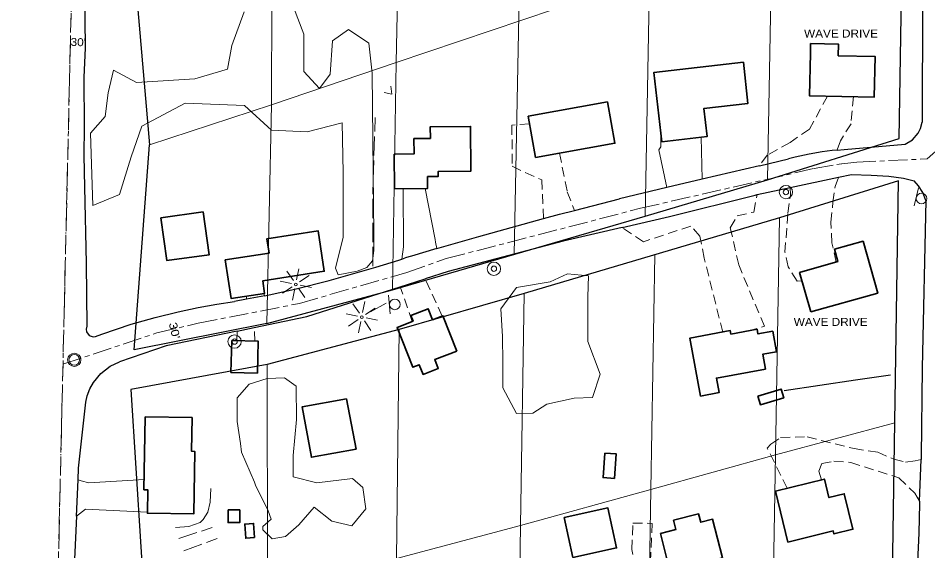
# Model space of a CAD drawing. Extents: x -861682 to -858969, y -1797841 to -1795153.
# Drawn here: x -861677 to -860995, y -1796483 to -1796083 of the extents above; entities that cross this region are included whole.
import ezdxf

# ---------------------------------------------------------------- set-up
doc = ezdxf.new("R2010")
doc.units = 0
doc.header["$LTSCALE"] = 2.4
for name, pattern in [('DOT_DASHED', [7.7, 5, -1.2, 0.3, -1.2]), ('LONG_DASH_SHORT_DASH', [9.9, 6, -1.2, 1.5, -1.2]), ('LONG_DASHED', [7.5, 6, -1.5]), ('MEDIUM_DASHED', [4.5, 3, -1.5])]:
    doc.linetypes.add(name, pattern=pattern)
for name, color, linetype, lineweight in [('10', 7, 'Continuous', 25), ('11', 7, 'Continuous', 13), ('12', 7, 'Continuous', 35), ('14', 7, 'Continuous', 25), ('17', 7, 'Continuous', 13), ('18', 7, 'Continuous', 13), ('21', 7, 'Continuous', 13), ('30', 7, 'Continuous', 13), ('31', 7, 'Continuous', 13), ('32', 7, 'LONG_DASH_SHORT_DASH', 13), ('36', 7, 'Continuous', 13), ('37', 7, 'Continuous', 13), ('42', 7, 'Continuous', 25), ('46', 7, 'Continuous', 13), ('52', 7, 'LONG_DASHED', 13), ('61', 7, 'Continuous', 13)]:
    doc.layers.add(name, color=color, linetype=linetype, lineweight=lineweight)
doc.layers.add('43', color=7, linetype='Continuous')

msp = doc.modelspace()

# ---------------------------------------------------------------- linework, layer by layer
at = {"layer": '10'}
for p, q in [((-860998.917, -1796071.72), (-860998.986, -1796161.04)), ((-861057.643, -1796181.638), (-861011.836, -1796177.693)), ((-861062.884, -1796182.084), (-861057.643, -1796181.638)), ((-861121.116, -1796193.796), (-861099.17, -1796188.618)), ((-861121.116, -1796193.796), (-861164.05, -1796203.927)), ((-861164.05, -1796203.927), (-861190.523, -1796210.174)), ((-861190.523, -1796210.174), (-861226.034, -1796218.554)), ((-861389.178, -1796263.819), (-861386.564, -1796262.963)), ((-861491.879, -1796291.281), (-861505.478, -1796293.954)), ((-861505.478, -1796293.954), (-861514.586, -1796295.745)), ((-861512.641, -1796317.835), (-861499.825, -1796315.144)), ((-861000.983, -1796445.525), (-860999.845, -1796414.115)), ((-861632.978, -1796456.776), (-861631.833, -1796429.359))]:
    msp.add_line(p, q, dxfattribs=at)
for points in [[(-861626.717, -1796064.684), (-861626.785, -1796084.061), (-861626.599, -1796105.326), (-861627.586, -1796127.546), (-861627.262, -1796164.642), (-861627.547, -1796186.147), (-861627.104, -1796209.773), (-861625.659, -1796266.943), (-861625.247, -1796314.198)], [(-861011.836, -1796177.693), (-861006.222, -1796174.249), (-861001.937, -1796169.248), (-861000.248, -1796165.865), (-860998.986, -1796161.04)], [(-861062.884, -1796182.084), (-861066.426, -1796182.387), (-861074.079, -1796183.353), (-861083.855, -1796185.016), (-861094.334, -1796187.346), (-861099.17, -1796188.618)], [(-861122.807, -1796215.423), (-861097.992, -1796210.128), (-861061.784, -1796202.403)], [(-861061.784, -1796202.403), (-861052.101, -1796200.338), (-861037.221, -1796200.751), (-861023.992, -1796201.642), (-861013.123, -1796203.016), (-861005.085, -1796205.108)], [(-860996.34, -1796219.944), (-860998.578, -1796213.737), (-861001.692, -1796208.773), (-861005.085, -1796205.108)], [(-861282.823, -1796233.418), (-861270.848, -1796230.126), (-861259.703, -1796227.248), (-861226.034, -1796218.554)], [(-861223.961, -1796240.056), (-861188.477, -1796231.823), (-861124.305, -1796215.743), (-861122.807, -1796215.423)], [(-860996.34, -1796219.944), (-860999.09, -1796345.364), (-860999.768, -1796411.964), (-860999.845, -1796414.115)], [(-861362.844, -1796255.976), (-861331.414, -1796246.777), (-861282.823, -1796233.418)], [(-861223.961, -1796240.056), (-861268.227, -1796250.327), (-861354.335, -1796273.108), (-861371.735, -1796278.648)], [(-861362.844, -1796255.976), (-861381.777, -1796261.518), (-861386.564, -1796262.963)], [(-861491.879, -1796291.281), (-861468.213, -1796286.021), (-861443.62, -1796279.889), (-861408.637, -1796269.966), (-861391.315, -1796264.519), (-861389.178, -1796263.819)], [(-861499.825, -1796315.144), (-861460.237, -1796306.831), (-861390.319, -1796284.566), (-861371.735, -1796278.648)], [(-861618.799, -1796321.938), (-861614.111, -1796320.199), (-861591.992, -1796312.739), (-861573.992, -1796307.552), (-861556.874, -1796303.329), (-861541.775, -1796300.162), (-861527.669, -1796297.666), (-861514.586, -1796295.745)], [(-861625.247, -1796314.198), (-861625.866, -1796316.297), (-861625.607, -1796318.471), (-861623.569, -1796321.208), (-861620.466, -1796322.194), (-861618.799, -1796321.938)], [(-861512.641, -1796317.835), (-861565.713, -1796328.981), (-861600.853, -1796340.93)], [(-861626.001, -1796371.259), (-861624.907, -1796366.383), (-861622.988, -1796361.235), (-861620.351, -1796356.402), (-861614.782, -1796349.593), (-861607.813, -1796344.224), (-861600.853, -1796340.93)], [(-861631.833, -1796429.359), (-861631.47, -1796420.638), (-861626.001, -1796371.259)], [(-861000.983, -1796445.525), (-861001.043, -1796447.157), (-861001.661, -1796469.594), (-861002.519, -1796491.087)], [(-861632.978, -1796456.776), (-861634.93, -1796500.001), (-861632.961, -1796578.634), (-861632.226, -1796643.811)]]:
    msp.add_lwpolyline(points, dxfattribs=at)
at = {"layer": '11'}
msp.add_line((-861164.824, -1796172.414), (-861164.05, -1796203.927), dxfattribs=at)
at = {"layer": '11', "linetype": 'MEDIUM_DASHED'}
for p, q in [((-861358.792, -1796306.543), (-861371.735, -1796278.648)), ((-861381.39, -1796310.665), (-861390.319, -1796284.566)), ((-861505.474, -1796291.618), (-861505.478, -1796293.954)), ((-861492.882, -1796289.663), (-861491.879, -1796291.281)), ((-861512.702, -1796325.105), (-861512.641, -1796317.835)), ((-861499.329, -1796325.449), (-861499.825, -1796315.144))]:
    msp.add_line(p, q, dxfattribs=at)
for points in [[(-861069.954, -1796141.504), (-861083.533, -1796166.269), (-861098.096, -1796176.321), (-861115.262, -1796185.923), (-861121.116, -1796193.796)], [(-861050.526, -1796141.909), (-861052.378, -1796162.216), (-861060.3, -1796175.046), (-861062.884, -1796182.084)], [(-861293.37, -1796162.231), (-861306.622, -1796163.258), (-861306.352, -1796194.21), (-861284.287, -1796204.414), (-861282.823, -1796233.418)], [(-861270.953, -1796184.314), (-861265.068, -1796213.462), (-861259.703, -1796227.248)], [(-861063.426, -1796266.105), (-861066.774, -1796251.645), (-861067.545, -1796236.061), (-861065.951, -1796221.177), (-861064.345, -1796209.362), (-861061.784, -1796202.403)], [(-861089.212, -1796280.014), (-861092.873, -1796280.325), (-861099.528, -1796269.725), (-861101.934, -1796258.634), (-861099.69, -1796229.341), (-861097.855, -1796215.636), (-861097.992, -1796210.128)], [(-861129.856, -1796317.781), (-861117.298, -1796314.195), (-861136.612, -1796268.22), (-861142.864, -1796240.378), (-861137.704, -1796231.383), (-861125.199, -1796228.499), (-861122.807, -1796215.423)], [(-861148.558, -1796318.544), (-861162.374, -1796263.128), (-861165.746, -1796246.61), (-861172.389, -1796239.08), (-861208.003, -1796250.794), (-861223.961, -1796240.056)], [(-861100.23, -1796435.756), (-861115.277, -1796405.579), (-861112.455, -1796402.733), (-861105.153, -1796397.745), (-861085.318, -1796397.193), (-861050.094, -1796406.026), (-861032.371, -1796408.789), (-861020.306, -1796413.936), (-861011.559, -1796416.263), (-861004.242, -1796415.289), (-860999.845, -1796414.115)], [(-861074.406, -1796429.431), (-861076.476, -1796422.898), (-861074.374, -1796417.222), (-861065.17, -1796415.532), (-861052.65, -1796416.426), (-861016.471, -1796427.853), (-861004.617, -1796439.378), (-861000.983, -1796445.525)], [(-861233.154, -1796499.634), (-861229.702, -1796551.748), (-861228.27, -1796555.521), (-861223.069, -1796556.917), (-861215.041, -1796556.413), (-861208.908, -1796554.735), (-861209.767, -1796517.189), (-861216.757, -1796481.792), (-861215.892, -1796461.951), (-861201.485, -1796462.129), (-861202.778, -1796493.072), (-861202.933, -1796513.383), (-861200.514, -1796527.779), (-861199.533, -1796536.749), (-861196.438, -1796542.877), (-861186.679, -1796553.213)]]:
    msp.add_lwpolyline(points, dxfattribs=at)
at = {"layer": '11'}
for points in [[(-861194.866, -1796170.493), (-861194.949, -1796179.531), (-861196.582, -1796181.908), (-861190.523, -1796210.174)], [(-861388.199, -1796210.992), (-861387.817, -1796254.704), (-861389.178, -1796263.819)], [(-861371.512, -1796210.846), (-861364.001, -1796249.061), (-861363.982, -1796251.188), (-861362.844, -1796255.976)], [(-861582.326, -1796429.236), (-861623.632, -1796431.706), (-861629.542, -1796430.313), (-861631.833, -1796429.359)], [(-861579.838, -1796453.65), (-861626.151, -1796451.554), (-861632.978, -1796456.776)]]:
    msp.add_lwpolyline(points, dxfattribs=at)
at = {"layer": '12'}
for points in [[(-861082.85, -1796109.315), (-861083.516, -1796141.221), (-861035.033, -1796142.233), (-861034.397, -1796111.756), (-861062.023, -1796111.179), (-861061.842, -1796102.525), (-861082.699, -1796102.089)], [(-861194.273, -1796175.743), (-861160.28, -1796171.901), (-861162.672, -1796150.738), (-861129.623, -1796147.003), (-861133.108, -1796116.168), (-861200.15, -1796123.746)], [(-861294.394, -1796156.533), (-861234.941, -1796145.853), (-861229.374, -1796176.846), (-861288.827, -1796187.525)], [(-861394.806, -1796185.058), (-861394.579, -1796211.048), (-861369.769, -1796210.831), (-861369.848, -1796201.853), (-861361.815, -1796201.782), (-861361.848, -1796198.002), (-861337.275, -1796197.787), (-861337.569, -1796164.237), (-861367.812, -1796164.502), (-861367.735, -1796173.243), (-861380.022, -1796173.351), (-861379.92, -1796184.927)], [(-861569.719, -1796232.9), (-861565.185, -1796264.996), (-861533.508, -1796260.521), (-861538.042, -1796228.425)], [(-861521.476, -1796264.378), (-861516.969, -1796293.403), (-861491.967, -1796289.521), (-861493.425, -1796280.133), (-861447.226, -1796272.958), (-861451.949, -1796242.549), (-861490.27, -1796248.501), (-861488.597, -1796259.272)], [(-861082.624, -1796303.426), (-861032.378, -1796289.291), (-861043.313, -1796250.421), (-861064.771, -1796256.458), (-861062.157, -1796265.748), (-861090.947, -1796273.849)], [(-861347.954, -1796332.829), (-861364.459, -1796339.271), (-861361.864, -1796345.919), (-861373.242, -1796350.36), (-861376.093, -1796343.055), (-861380.984, -1796344.964), (-861392.655, -1796315.062), (-861380.639, -1796310.372), (-861382.289, -1796306.146), (-861369.303, -1796301.076), (-861366.061, -1796309.381), (-861358.292, -1796306.348)], [(-861116.459, -1796346.306), (-861153.274, -1796353.066), (-861151.264, -1796364.011), (-861165.157, -1796366.562), (-861173.145, -1796323.059), (-861142.955, -1796317.516), (-861142.48, -1796320.101), (-861122.802, -1796316.485), (-861122.161, -1796319.975), (-861111.123, -1796317.948), (-861108.304, -1796333.301), (-861118.503, -1796335.174)], [(-861516.606, -1796325.005), (-861517.219, -1796348.86), (-861497.411, -1796349.369), (-861496.798, -1796325.514)], [(-861122.282, -1796366.64), (-861104.827, -1796361.374), (-861102.865, -1796367.876), (-861120.319, -1796373.143)], [(-861430.467, -1796368.583), (-861423.467, -1796406.341), (-861456.923, -1796412.543), (-861463.922, -1796374.785)], [(-861581.557, -1796382.178), (-861546.366, -1796382.745), (-861546.773, -1796408.035), (-861544.377, -1796408.074), (-861545.142, -1796455.049), (-861579.852, -1796454.484), (-861579.566, -1796436.929), (-861582.451, -1796436.882)], [(-861236.885, -1796409.371), (-861238.229, -1796427.797), (-861229.774, -1796428.414), (-861228.43, -1796409.988)], [(-861109.006, -1796437.905), (-861099.642, -1796476.126), (-861065.766, -1796467.827), (-861065.238, -1796469.983), (-861051.027, -1796466.503), (-861057.527, -1796439.959), (-861068.904, -1796442.745), (-861072.291, -1796428.914)], [(-861519.402, -1796452.069), (-861519.364, -1796461.516), (-861510.626, -1796461.481), (-861510.664, -1796452.034)], [(-861267.392, -1796457.669), (-861260.896, -1796487.636), (-861228.124, -1796480.532), (-861234.621, -1796450.565)], [(-861195.314, -1796469.661), (-861187.156, -1796501.746), (-861170.447, -1796497.498), (-861171.393, -1796493.779), (-861148.8, -1796488.032), (-861156.184, -1796459.003), (-861165.008, -1796461.247), (-861166.603, -1796454.974), (-861185.365, -1796459.745), (-861183.601, -1796466.682)], [(-861499.482, -1796472.772), (-861506.092, -1796473.271), (-861506.89, -1796462.7), (-861500.28, -1796462.201)]]:
    msp.add_lwpolyline(points, close=True, dxfattribs=at)
at = {"layer": '14'}
msp.add_lwpolyline([(-861102.462, -1796362.31), (-861049.121, -1796354.303), (-861022.685, -1796350.654)], dxfattribs=at)
at = {"layer": '17'}
for p, q in [((-861470.421, -1796279.92), (-861475.211, -1796272.792)), ((-861467.961, -1796279.46), (-861466.235, -1796271.06)), ((-861465.761, -1796280.86), (-861458.665, -1796276.12)), ((-861471.921, -1796282.12), (-861480.383, -1796280.446)), ((-861471.381, -1796284.62), (-861478.607, -1796289.476)), ((-861471.001, -1796294.58), (-861469.321, -1796285.98)), ((-861466.661, -1796285.52), (-861461.861, -1796292.734)), ((-861465.321, -1796283.38), (-861456.841, -1796285.104)), ((-861420.942, -1796304.475), (-861425.732, -1796297.347)), ((-861418.482, -1796304.015), (-861416.756, -1796295.615)), ((-861422.442, -1796306.675), (-861430.904, -1796305.001)), ((-861416.282, -1796305.415), (-861409.186, -1796300.675)), ((-861421.902, -1796309.175), (-861429.128, -1796314.031)), ((-861421.522, -1796319.135), (-861419.842, -1796310.535)), ((-861417.182, -1796310.075), (-861412.382, -1796317.289)), ((-861415.842, -1796307.935), (-861407.362, -1796309.659))]:
    msp.add_line(p, q, dxfattribs=at)
for centre in [(-861468.621, -1796282.82), (-861419.142, -1796307.375)]:
    msp.add_circle(centre, 1, dxfattribs=at)
at = {"layer": '18'}
msp.add_lwpolyline([(-861470.438, -1796074.896), (-861462.699, -1796095.15), (-861462.456, -1796123.031), (-861450.767, -1796135.688), (-861442.826, -1796124.986), (-861441.155, -1796099.924), (-861429.177, -1796091.549), (-861413.964, -1796101.813), (-861411.405, -1796124.239), (-861410.519, -1796198.664), (-861410.112, -1796245.21), (-861410.007, -1796257.261), (-861411.12, -1796265.068), (-861415.33, -1796270.067), (-861422.63, -1796272.966), (-861436.784, -1796275.689), (-861438.955, -1796270.51), (-861433.015, -1796247.301), (-861433.201, -1796198.862), (-861433.764, -1796161.532), (-861460.169, -1796168.379), (-861486.881, -1796167.195), (-861507.13, -1796148.468), (-861551.568, -1796146.73), (-861584.026, -1796164.027), (-861592.095, -1796187.018), (-861600.826, -1796215.45), (-861620.839, -1796223.658), (-861622.496, -1796169.325), (-861611.498, -1796156.942), (-861609.292, -1796138.964), (-861605.186, -1796122.151), (-861588.093, -1796131.217), (-861544.166, -1796128.47), (-861519.89, -1796121.406), (-861516.5, -1796103.654), (-861507.27, -1796078.29)], dxfattribs=at)
for points in [[(-861313.364, -1796360.322), (-861313.439, -1796341.429), (-861313.754, -1796321.829), (-861315.018, -1796301.051), (-861303.037, -1796285.18), (-861278.022, -1796280.829), (-861264.82, -1796274.872), (-861249.227, -1796276.463), (-861249.637, -1796292.051), (-861249.739, -1796325.587), (-861240.43, -1796350.11), (-861246.264, -1796367.61), (-861259.96, -1796368.137), (-861280.487, -1796372.706), (-861290.852, -1796379.361), (-861303.131, -1796379.646)], [(-861487.02, -1796459.025), (-861489.407, -1796452.658), (-861498.93, -1796433.567), (-861499.648, -1796431.208), (-861509.184, -1796408.811), (-861510.156, -1796402.202), (-861512.583, -1796385.68), (-861512.654, -1796367.968), (-861503.485, -1796357.777), (-861490.041, -1796353.472), (-861477.054, -1796352.948), (-861468.291, -1796359.289), (-861467.955, -1796384.085), (-861470.68, -1796411.254), (-861470.616, -1796427.313), (-861452.886, -1796431.729), (-861426.212, -1796428.552), (-861418.392, -1796435.133), (-861416.203, -1796451.184), (-861426.543, -1796463.978), (-861441.671, -1796460.496), (-861454.938, -1796449.922), (-861466.221, -1796463.192), (-861476.341, -1796471.971), (-861486.253, -1796473.664), (-861493.364, -1796467.08), (-861493.375, -1796464.482)]]:
    msp.add_lwpolyline(points, close=True, dxfattribs=at)
at = {"layer": '21'}
for p, q in [((-861005.153, -1796223.893), (-861001.807, -1796210.295)), ((-861397.905, -1796304.871), (-861398.994, -1796290.909))]:
    msp.add_line(p, q, dxfattribs=at)
for centre in [(-860999.6, -1796218.312), (-861394.383, -1796297.829)]:
    msp.add_circle(centre, 4, dxfattribs=at)
at = {"layer": '30'}
for p, q in [((-861297.927, -1795905.066), (-861304.865, -1796260.285)), ((-861389.894, -1795940.687), (-861393.277, -1796116.269)), ((-861486.117, -1795980.981), (-861486.75, -1796148.044)), ((-861114.964, -1796204.326), (-861111.76, -1796021.472)), ((-861206.656, -1796231.652), (-861203.476, -1796051.939)), ((-861395.989, -1796286.853), (-861393.277, -1796116.269)), ((-861578.206, -1796177.971), (-861486.75, -1796148.044)), ((-861490.231, -1796312.242), (-861486.75, -1796148.044)), ((-861105.996, -1796232.968), (-861109.061, -1796410.798)), ((-861199.431, -1796260.627), (-861202.355, -1796436.746)), ((-861297.512, -1796289.662), (-861300.148, -1796463.638)), ((-861391.12, -1796316.601), (-861393.124, -1796488.603)), ((-861489.939, -1796343.018), (-861489.711, -1796514.077)), ((-861019.543, -1796386.625), (-861109.061, -1796410.798)), ((-861111.716, -1796571.574), (-861109.061, -1796410.798)), ((-861205.179, -1796600.931), (-861202.355, -1796436.746)), ((-861302.863, -1796629.54), (-861300.148, -1796463.638))]:
    msp.add_line(p, q, dxfattribs=at)
for points in [[(-861486.75, -1796148.044), (-861393.277, -1796116.269), (-861203.476, -1796051.939), (-861111.76, -1796021.472)], [(-861489.711, -1796514.077), (-861393.124, -1796488.603), (-861300.148, -1796463.638), (-861202.355, -1796436.746), (-861109.061, -1796410.798)]]:
    msp.add_lwpolyline(points, dxfattribs=at)
at = {"layer": '31'}
for centre, radius in [((-861101.17, -1796213.524), 5), ((-861101.17, -1796213.524), 2), ((-861320.099, -1796271.081), 5), ((-861320.099, -1796271.081), 2), ((-861514.479, -1796325.705), 5), ((-861514.479, -1796325.705), 2)]:
    msp.add_circle(centre, radius, dxfattribs=at)
at = {"layer": '32'}
for points in [[(-861635.972, -1796031.868), (-861668.34, -1797434.932), (-861671.877, -1797797.365)], [(-861643.143, -1796342.695), (-861572.843, -1796319.262), (-861541.729, -1796312.003), (-861465.815, -1796297.069), (-861385.338, -1796273.839), (-861355.885, -1796263.468), (-861210.278, -1796225.718), (-861080.021, -1796195.85), (-861059.279, -1796192.323), (-861048.079, -1796191.078), (-860995.395, -1796188.589), (-860973.824, -1796169.507), (-860942.711, -1796163.285), (-860814.942, -1796124.705), (-860733.443, -1796101.033)]]:
    msp.add_lwpolyline(points, dxfattribs=at)
at = {"layer": '36'}
for radius in [5, 4]:
    msp.add_circle((-861634.631, -1796339.412), radius, dxfattribs=at)
at = {"layer": '37'}
msp.add_lwpolyline([(-861397.38, -1796134.181), (-861396.616, -1796140.179), (-861402.475, -1796138.685)], dxfattribs=at)
at = {"layer": '42'}
for p, q in [((-861206.656, -1796231.652), (-861114.964, -1796204.326)), ((-861395.989, -1796286.853), (-861206.656, -1796231.652)), ((-861105.996, -1796232.968), (-861297.512, -1796289.662)), ((-861490.231, -1796312.242), (-861395.989, -1796286.853)), ((-861297.512, -1796289.662), (-861391.12, -1796316.601)), ((-861391.12, -1796316.601), (-861489.939, -1796343.018))]:
    msp.add_line(p, q, dxfattribs=at)
for points in [[(-861486.117, -1795980.981), (-861590.789, -1796033.063), (-861578.206, -1796177.971)], [(-861114.964, -1796204.326), (-861016.328, -1796173.211), (-861013.265, -1795989.396)], [(-861490.231, -1796312.242), (-861589.773, -1796331.813), (-861578.206, -1796177.971)], [(-861111.716, -1796571.574), (-861021.724, -1796534.239), (-861016.862, -1796205.211), (-861105.996, -1796232.968)], [(-861489.939, -1796343.018), (-861592.302, -1796361.775), (-861581.116, -1796538.693)]]:
    msp.add_lwpolyline(points, dxfattribs=at)
at = {"layer": '52'}
for p, q in [((-861412.546, -1796303.334), (-861400.763, -1796296.91)), ((-861556.394, -1796473.473), (-861531.393, -1796465.343)), ((-861552.579, -1796482.667), (-861527.581, -1796473.592))]:
    msp.add_line(p, q, dxfattribs=at)
for points in [[(-861410.849, -1796269.083), (-861410.707, -1796204.101), (-861408.988, -1796157.536)], [(-861558.789, -1796465.217), (-861548.873, -1796464.469), (-861540.384, -1796461.364), (-861538.031, -1796459.23), (-861534.51, -1796453.784), (-861532.887, -1796446.22), (-861532.22, -1796436.062)]]:
    msp.add_lwpolyline(points, dxfattribs=at)
at = {"layer": '61', "linetype": 'DOT_DASHED'}
msp.add_line((-861615.801, -1795157.51), (-861676.699, -1797797.295), dxfattribs=at)

# ---------------------------------------------------------------- texts
at = {"layer": '43'}
for rotation, width, p in [(358.069, 1.1, (-861637.494, -1796103.81)), (283.203, 1.2, (-861563.814, -1796312.063))]:
    msp.add_text("30'", height=6, rotation=rotation, dxfattribs=dict(at, width=width)).set_placement(p)
at = {"layer": '46', "width": 1.1}
for p in [(-861087.588, -1796097.55), (-861095.33, -1796313.964)]:
    msp.add_text('WAVE DRIVE', height=6, dxfattribs=at).set_placement(p)

doc.saveas('drawing.dxf')
